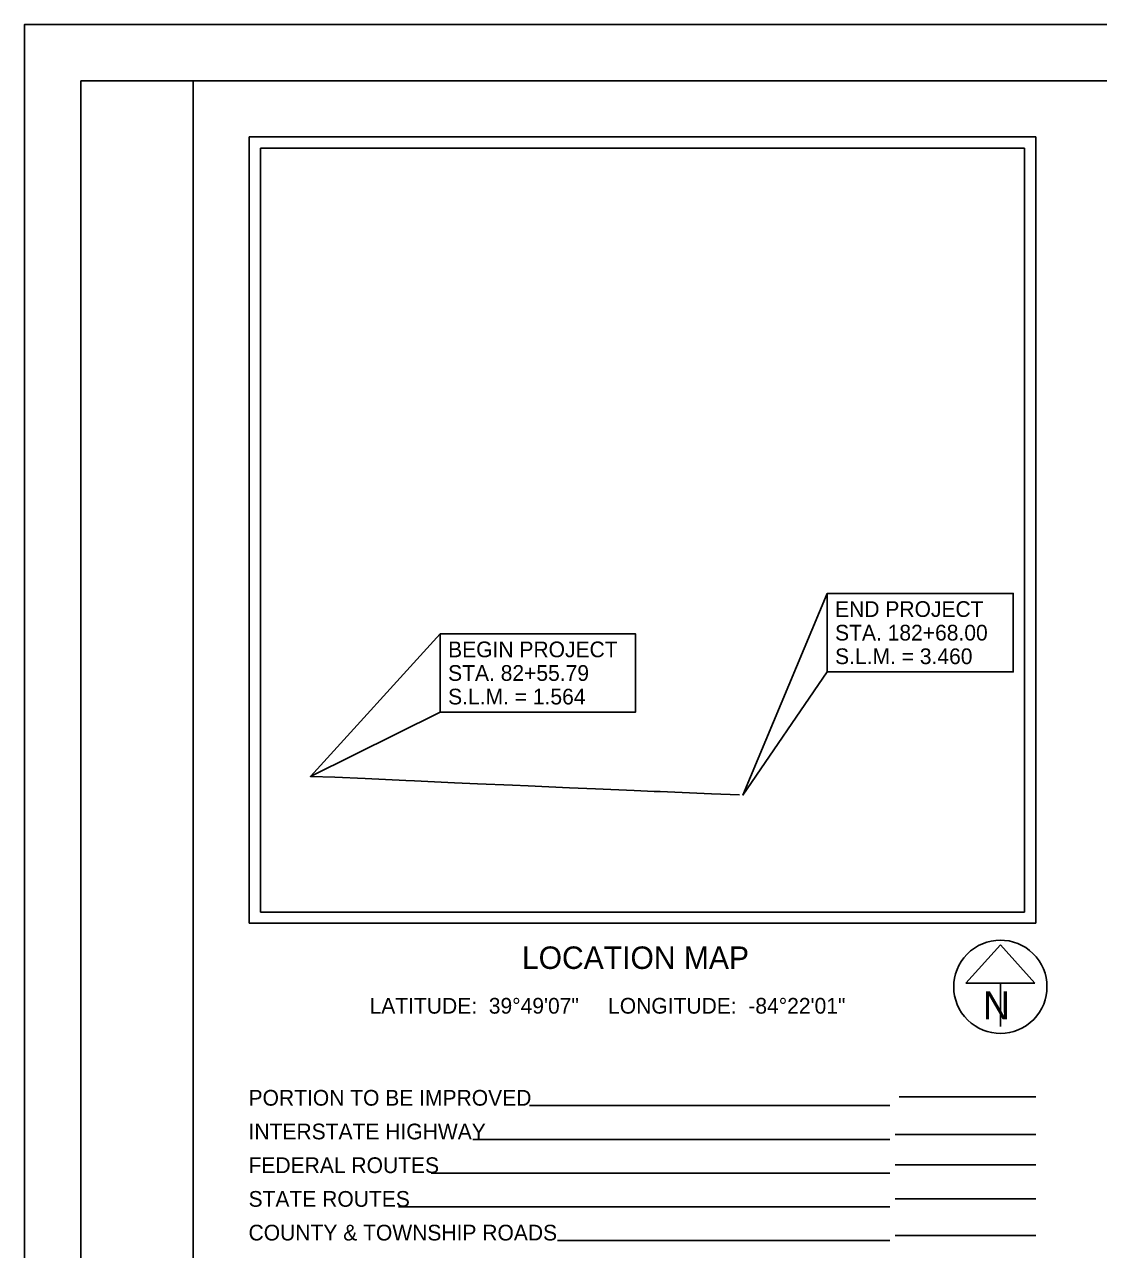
# Model space of a CAD drawing. Extents: x 0 to 42, y 0 to 22.
# Drawn here: x 0 to 9.56, y 11.1 to 22 of the extents above; entities that cross this region are included whole.
import ezdxf

# ---------------------------------------------------------------- set-up
doc = ezdxf.new("R2010")
doc.units = 0
for name, color, linetype in [('GM_X_Adjacent_County', 7, 'Continuous'), ('GM_X_County', 7, 'Continuous'), ('GM_X_Minor_River', 7, 'Continuous'), ('GM_X_Section', 7, 'Continuous'), ('GM_X_Township', 7, 'Continuous')]:
    doc.layers.add(name, color=color, linetype=linetype)

msp = doc.modelspace()

# ---------------------------------------------------------------- linework, layer by layer
at = {"layer": 'GM_X_Adjacent_County'}
for points in [[(7.144, 16.237), (6.393, 15.142), (7.144, 16.937)], [(3.7, 16.578), (2.545, 15.307), (3.7, 15.878)], [(3.7, 15.878), (5.437, 15.878), (5.437, 16.578), (3.7, 16.578)]]:
    msp.add_lwpolyline(points, close=True, dxfattribs=at)
at = {"layer": 'GM_X_County'}
for points in [[(0.5, 21.5), (1.5, 21.5), (1.5, 0.5), (0.5, 0.5)], [(1.5, 21.5), (33.5, 21.5), (33.5, 0.5), (1.5, 0.5)]]:
    msp.add_lwpolyline(points, close=True, dxfattribs=at)
at = {"layer": 'GM_X_Minor_River'}
msp.add_lwpolyline([(7.144, 16.237), (8.799, 16.237), (8.799, 16.937), (7.144, 16.937)], close=True, dxfattribs=at)
at = {"layer": 'GM_X_Section'}
msp.add_lwpolyline([(0, 0), (34, 0), (34, 22), (0, 22)], close=True, dxfattribs=at)
at = {"layer": 'GM_X_Township'}
for p, q in [((2, 21), (9, 21)), ((2, 21), (2, 14)), ((9, 21), (9, 14)), ((2.1, 20.9), (2.1, 14.1)), ((2.1, 20.9), (8.9, 20.9)), ((8.9, 20.9), (8.9, 14.1)), ((2.1, 14.1), (8.9, 14.1)), ((2.1, 14.1), (2.1, 14.1)), ((2, 14), (9, 14)), ((8.685, 13.809), (8.377, 13.468)), ((8.992, 13.468), (8.685, 13.809)), ((8.377, 13.468), (8.992, 13.468)), ((8.685, 13.468), (8.685, 13.081)), ((8.685, 13.435), (8.685, 13.435)), ((8.685, 13.435), (8.685, 13.435)), ((7.783, 12.455), (9, 12.455)), ((7.7, 12.377), (4.494, 12.377)), ((9, 12.121), (7.75, 12.121)), ((7.7, 12.077), (3.99, 12.077)), ((7.7, 11.777), (3.619, 11.777)), ((9, 11.849), (7.75, 11.849)), ((7.7, 11.477), (3.329, 11.477)), ((9, 11.549), (7.75, 11.549)), ((7.7, 11.177), (4.745, 11.177)), ((9, 11.222), (7.75, 11.222))]:
    msp.add_line(p, q, dxfattribs=at)
msp.add_lwpolyline([(2.545, 15.307), (2.763, 15.3), (3.032, 15.289), (3.394, 15.27), (3.471, 15.268), (3.828, 15.251), (4.032, 15.242), (4.344, 15.229), (4.483, 15.224), (4.849, 15.207), (5.083, 15.197), (5.427, 15.182), (5.604, 15.174), (5.656, 15.172), (5.917, 15.16), (6.115, 15.153), (6.363, 15.143)], dxfattribs=at)
msp.add_arc((8.685, 13.435), 0.415, 129.7798, 129.7633, dxfattribs=at)

# ---------------------------------------------------------------- texts
at = {"layer": 'GM_X_Adjacent_County'}
for s, height, p in [('BEGIN PROJECT', 0.14, (3.77, 16.368)), ('STA. 82+55.79', 0.14, (3.77, 16.158)), ('S.L.M. = 1.564', 0.14, (3.77, 15.948)), ('LOCATION MAP', 0.2, (4.427, 13.594)), ('LATITUDE:  39°49\'07"     LONGITUDE:  -84°22\'01"', 0.14, (3.071, 13.196)), ('PORTION TO BE IMPROVED', 0.14, (1.994, 12.377)), ('INTERSTATE HIGHWAY', 0.14, (1.994, 12.077)), ('FEDERAL ROUTES', 0.14, (1.994, 11.777)), ('STATE ROUTES', 0.14, (1.994, 11.477)), ('COUNTY & TOWNSHIP ROADS', 0.14, (1.994, 11.177))]:
    msp.add_text(s, height=height, dxfattribs=at).set_placement(p)
at = {"layer": 'GM_X_Minor_River'}
for s, p in [('END PROJECT', (7.214, 16.727)), ('STA. 182+68.00', (7.214, 16.517)), ('S.L.M. = 3.460', (7.214, 16.307))]:
    msp.add_text(s, height=0.14, rotation=360, dxfattribs=at).set_placement(p)
at = {"layer": 'GM_X_Township'}
msp.add_text('N', height=0.25, dxfattribs=at).set_placement((8.529, 13.144))

doc.saveas('drawing.dxf')
